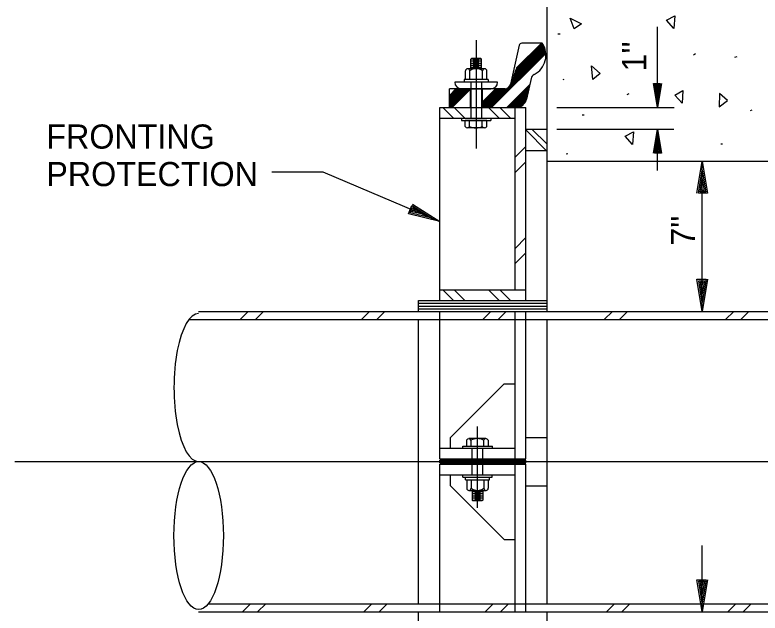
# Model space of a CAD drawing. Extents: x 22388.1 to 22405.7, y 22369.6 to 22390.4.
# Drawn here: x 22393.499 to 22394.947, y 22387.97 to 22389.132 of the extents above; entities that cross this region are included whole.
import ezdxf

# ---------------------------------------------------------------- set-up
doc = ezdxf.new("R2010")
doc.units = 0
for name, color, linetype in [('Level 1', 7, 'Continuous'), ('Level 2', 7, 'Continuous'), ('Level 4', 7, 'Continuous'), ('Level 44', 7, 'Continuous'), ('Level 50', 7, 'Continuous'), ('Level 7', 7, 'Continuous')]:
    doc.layers.add(name, color=color, linetype=linetype)

msp = doc.modelspace()

# ---------------------------------------------------------------- linework, layer by layer
at = {"layer": 'Level 1'}
for p, q in [((22394.7476, 22388.9518), (22394.7476, 22389.1086)), ((22394.3954, 22389.0827), (22394.3954, 22388.872)), ((22394.5267, 22389.0714), (22394.4678, 22389.0125)), ((22394.5264, 22389.072), (22394.4683, 22389.0139)), ((22394.5261, 22389.0726), (22394.4688, 22389.0153)), ((22394.5258, 22389.0732), (22394.4693, 22389.0167)), ((22394.5255, 22389.0738), (22394.4698, 22389.0182)), ((22394.5251, 22389.0744), (22394.4703, 22389.0196)), ((22394.5248, 22389.075), (22394.4708, 22389.021)), ((22394.5244, 22389.0756), (22394.4713, 22389.0224)), ((22394.5241, 22389.0761), (22394.4718, 22389.0239)), ((22394.5237, 22389.0767), (22394.4723, 22389.0253)), ((22394.5229, 22389.0768), (22394.4728, 22389.0267)), ((22394.522, 22389.0768), (22394.4733, 22389.0281)), ((22394.53, 22389.062), (22394.4198, 22388.9518)), ((22394.5301, 22389.0614), (22394.4205, 22388.9518)), ((22394.5302, 22389.0608), (22394.4212, 22388.9518)), ((22394.5303, 22389.0602), (22394.4219, 22388.9518)), ((22394.5304, 22389.0596), (22394.4226, 22388.9518)), ((22394.5305, 22389.0589), (22394.4233, 22388.9518)), ((22394.5306, 22389.0583), (22394.424, 22388.9518)), ((22394.5306, 22389.0577), (22394.4247, 22388.9518)), ((22394.5307, 22389.057), (22394.4254, 22388.9518)), ((22394.5298, 22389.0625), (22394.4606, 22388.9933)), ((22394.5296, 22389.0633), (22394.4618, 22388.9954)), ((22394.5295, 22389.064), (22394.4623, 22388.9968)), ((22394.5293, 22389.0647), (22394.4628, 22388.9982)), ((22394.5291, 22389.0654), (22394.4633, 22388.9997)), ((22394.5288, 22389.0661), (22394.4638, 22389.0011)), ((22394.5286, 22389.0668), (22394.4643, 22389.0025)), ((22394.5284, 22389.0675), (22394.4648, 22389.0039)), ((22394.5281, 22389.0682), (22394.4653, 22389.0054)), ((22394.5279, 22389.0689), (22394.4658, 22389.0068)), ((22394.5276, 22389.0695), (22394.4663, 22389.0082)), ((22394.5273, 22389.0701), (22394.4668, 22389.0096)), ((22394.527, 22389.0708), (22394.4673, 22389.011)), ((22394.385, 22389.0459), (22394.3861, 22389.0471)), ((22394.4058, 22389.0461), (22394.385, 22389.0461)), ((22394.385, 22389.0273), (22394.385, 22389.0459)), ((22394.4047, 22389.0471), (22394.3861, 22389.0471)), ((22394.4006, 22389.044), (22394.3897, 22389.044)), ((22394.4058, 22389.046), (22394.4047, 22389.0471)), ((22394.4058, 22389.0273), (22394.4058, 22389.046)), ((22394.4058, 22389.0419), (22394.385, 22389.0419)), ((22394.4058, 22389.0377), (22394.385, 22389.0377)), ((22394.4058, 22389.0336), (22394.385, 22389.0336)), ((22394.4058, 22389.0294), (22394.385, 22389.0294)), ((22394.4006, 22389.0398), (22394.3897, 22389.0398)), ((22394.4006, 22389.0356), (22394.3897, 22389.0356)), ((22394.4006, 22389.0315), (22394.3897, 22389.0315)), ((22394.3746, 22389.0065), (22394.3746, 22389.0231)), ((22394.3746, 22389.0231), (22394.3746, 22389.0231)), ((22394.412, 22389.0273), (22394.3788, 22389.0273)), ((22394.383, 22389.0065), (22394.383, 22389.0231)), ((22394.4077, 22389.0065), (22394.4077, 22389.0231)), ((22394.4163, 22389.0065), (22394.4163, 22389.0231)), ((22394.4189, 22389.0065), (22394.372, 22389.0065)), ((22394.372, 22389.0065), (22394.372, 22389.0013)), ((22394.385, 22389.0013), (22394.385, 22388.9309)), ((22394.4058, 22389.0013), (22394.4058, 22388.9309)), ((22394.4189, 22389.0065), (22394.4189, 22389.0013)), ((22394.3795, 22388.9882), (22394.3433, 22388.9521)), ((22394.3788, 22388.9882), (22394.3433, 22388.9528)), ((22394.3781, 22388.9882), (22394.3433, 22388.9535)), ((22394.3774, 22388.9882), (22394.3433, 22388.9542)), ((22394.3767, 22388.9882), (22394.3433, 22388.9549)), ((22394.376, 22388.9882), (22394.3433, 22388.9556)), ((22394.3752, 22388.9882), (22394.3433, 22388.9563)), ((22394.3745, 22388.9882), (22394.3433, 22388.957)), ((22394.3738, 22388.9882), (22394.3433, 22388.9578)), ((22394.3731, 22388.9882), (22394.3433, 22388.9585)), ((22394.3724, 22388.9882), (22394.3433, 22388.9592)), ((22394.3717, 22388.9882), (22394.3433, 22388.9599)), ((22394.371, 22388.9882), (22394.3433, 22388.9606)), ((22394.3703, 22388.9882), (22394.3433, 22388.9613)), ((22394.3696, 22388.9882), (22394.3433, 22388.962)), ((22394.3689, 22388.9882), (22394.3433, 22388.9627)), ((22394.3682, 22388.9882), (22394.3433, 22388.9634)), ((22394.3675, 22388.9882), (22394.3433, 22388.9641)), ((22394.3668, 22388.9882), (22394.3433, 22388.9648)), ((22394.3661, 22388.9882), (22394.3433, 22388.9655)), ((22394.3653, 22388.9882), (22394.3433, 22388.9663)), ((22394.3646, 22388.9882), (22394.3433, 22388.9669)), ((22394.3639, 22388.9882), (22394.3433, 22388.9676)), ((22394.3632, 22388.9882), (22394.3433, 22388.9684)), ((22394.3625, 22388.9882), (22394.3433, 22388.9691)), ((22394.3618, 22388.9882), (22394.3433, 22388.9698)), ((22394.3611, 22388.9882), (22394.3433, 22388.9705)), ((22394.3604, 22388.9882), (22394.3433, 22388.9712)), ((22394.3597, 22388.9882), (22394.3433, 22388.9719)), ((22394.359, 22388.9882), (22394.3433, 22388.9726)), ((22394.3583, 22388.9882), (22394.3433, 22388.9733)), ((22394.3576, 22388.9882), (22394.3433, 22388.974)), ((22394.3569, 22388.9882), (22394.3433, 22388.9747)), ((22394.3562, 22388.9882), (22394.3433, 22388.9754)), ((22394.3802, 22388.9882), (22394.3437, 22388.9518)), ((22394.3809, 22388.9882), (22394.3445, 22388.9518)), ((22394.3816, 22388.9882), (22394.3452, 22388.9518)), ((22394.3823, 22388.9882), (22394.3459, 22388.9518)), ((22394.383, 22388.9882), (22394.3466, 22388.9518)), ((22394.3837, 22388.9882), (22394.3473, 22388.9518)), ((22394.3837, 22388.9875), (22394.348, 22388.9518)), ((22394.3837, 22388.9868), (22394.3487, 22388.9518)), ((22394.3837, 22388.9868), (22394.3487, 22388.9518)), ((22394.4435, 22388.9882), (22394.407, 22388.9518)), ((22394.4428, 22388.9882), (22394.4072, 22388.9526)), ((22394.4421, 22388.9882), (22394.4072, 22388.9533)), ((22394.4414, 22388.9882), (22394.4072, 22388.954)), ((22394.4407, 22388.9882), (22394.4072, 22388.9547)), ((22394.44, 22388.9882), (22394.4072, 22388.9554)), ((22394.4393, 22388.9882), (22394.4072, 22388.9561)), ((22394.4386, 22388.9882), (22394.4072, 22388.9568)), ((22394.4378, 22388.9882), (22394.4072, 22388.9575)), ((22394.4371, 22388.9882), (22394.4072, 22388.9583)), ((22394.4364, 22388.9882), (22394.4072, 22388.959)), ((22394.4357, 22388.9882), (22394.4072, 22388.9597)), ((22394.435, 22388.9882), (22394.4072, 22388.9604)), ((22394.4343, 22388.9882), (22394.4072, 22388.9611)), ((22394.4336, 22388.9882), (22394.4072, 22388.9618)), ((22394.4329, 22388.9882), (22394.4072, 22388.9625)), ((22394.4442, 22388.9882), (22394.4078, 22388.9518)), ((22394.4449, 22388.9882), (22394.4085, 22388.9518)), ((22394.4456, 22388.9882), (22394.4092, 22388.9518)), ((22394.4463, 22388.9882), (22394.4099, 22388.9518)), ((22394.447, 22388.9882), (22394.4106, 22388.9518)), ((22394.4478, 22388.9882), (22394.4113, 22388.9518)), ((22394.4485, 22388.9882), (22394.412, 22388.9518)), ((22394.4492, 22388.9882), (22394.4127, 22388.9518)), ((22394.4499, 22388.9882), (22394.4134, 22388.9518)), ((22394.4506, 22388.9882), (22394.4141, 22388.9518)), ((22394.4513, 22388.9882), (22394.4148, 22388.9518)), ((22394.452, 22388.9882), (22394.4155, 22388.9518)), ((22394.4527, 22388.9882), (22394.4162, 22388.9518)), ((22394.4537, 22388.9886), (22394.417, 22388.9518)), ((22394.4548, 22388.9889), (22394.4177, 22388.9518)), ((22394.4559, 22388.9893), (22394.4184, 22388.9518)), ((22394.4576, 22388.9903), (22394.4191, 22388.9518)), ((22394.4553, 22388.9518), (22394.4993, 22388.9957)), ((22394.456, 22388.9518), (22394.4991, 22388.9948)), ((22394.4568, 22388.9518), (22394.4989, 22388.9939)), ((22394.4575, 22388.9518), (22394.4987, 22388.993)), ((22394.4582, 22388.9518), (22394.4985, 22388.9921)), ((22394.4589, 22388.9518), (22394.4983, 22388.9912)), ((22394.4596, 22388.9518), (22394.4981, 22388.9903)), ((22394.4603, 22388.9518), (22394.4979, 22388.9894)), ((22394.461, 22388.9518), (22394.4977, 22388.9884)), ((22394.4617, 22388.9518), (22394.4975, 22388.9875)), ((22394.4624, 22388.9518), (22394.4973, 22388.9866)), ((22394.4631, 22388.9518), (22394.497, 22388.9857)), ((22394.4638, 22388.9518), (22394.4966, 22388.9846)), ((22394.4645, 22388.9518), (22394.4966, 22388.9839)), ((22394.4652, 22388.9518), (22394.4964, 22388.983)), ((22394.4659, 22388.9518), (22394.4962, 22388.9821)), ((22394.4666, 22388.9518), (22394.496, 22388.9812)), ((22394.4674, 22388.9518), (22394.4958, 22388.9803)), ((22394.4681, 22388.9518), (22394.4956, 22388.9793)), ((22394.4954, 22388.9784), (22394.4688, 22388.9518)), ((22394.4952, 22388.9775), (22394.4695, 22388.9518)), ((22394.495, 22388.9766), (22394.4702, 22388.9518)), ((22394.4948, 22388.9757), (22394.4709, 22388.9518)), ((22394.4946, 22388.9748), (22394.4716, 22388.9518)), ((22394.4944, 22388.9739), (22394.4724, 22388.9519)), ((22394.4942, 22388.973), (22394.473, 22388.9518)), ((22394.494, 22388.9721), (22394.4737, 22388.9518)), ((22394.4938, 22388.9711), (22394.4745, 22388.9519)), ((22394.4936, 22388.9702), (22394.4753, 22388.9519)), ((22394.4934, 22388.9693), (22394.4761, 22388.952)), ((22394.4932, 22388.9684), (22394.477, 22388.9522)), ((22394.493, 22388.9675), (22394.4779, 22388.9524)), ((22394.4927, 22388.9665), (22394.4789, 22388.9527)), ((22394.4923, 22388.9654), (22394.4799, 22388.9531)), ((22394.4917, 22388.9639), (22394.4815, 22388.9537)), ((22394.4906, 22388.9619), (22394.4835, 22388.9547)), ((22394.3516, 22388.9309), (22394.3308, 22388.9518)), ((22394.3737, 22388.9309), (22394.3528, 22388.9518)), ((22394.44, 22388.9309), (22394.4191, 22388.9518)), ((22394.462, 22388.9309), (22394.4412, 22388.9518)), ((22394.5523, 22388.9518), (22394.7801, 22388.9518)), ((22394.3668, 22388.9309), (22394.3668, 22388.927)), ((22394.3668, 22388.927), (22394.4241, 22388.927)), ((22394.416, 22388.927), (22394.3743, 22388.927)), ((22394.3743, 22388.9153), (22394.3743, 22388.927)), ((22394.3827, 22388.9152), (22394.3827, 22388.927)), ((22394.4073, 22388.9152), (22394.4073, 22388.927)), ((22394.416, 22388.9153), (22394.416, 22388.927)), ((22394.4241, 22388.9309), (22394.4241, 22388.927)), ((22394.4117, 22388.9125), (22394.3785, 22388.9125)), ((22394.5335, 22388.8667), (22394.4918, 22388.9084)), ((22394.5335, 22388.8804), (22394.5037, 22388.9101)), ((22394.5523, 22388.9101), (22394.7793, 22388.9101)), ((22394.7476, 22388.8298), (22394.7476, 22388.9101)), ((22394.471, 22388.8552), (22394.4918, 22388.8761)), ((22394.471, 22388.8258), (22394.4918, 22388.8466)), ((22394.8346, 22388.5559), (22394.8346, 22388.8476)), ((22394.471, 22388.6784), (22394.4918, 22388.6993)), ((22394.471, 22388.649), (22394.4918, 22388.6698)), ((22394.3516, 22388.5768), (22394.3308, 22388.5976)), ((22394.3736, 22388.5768), (22394.3528, 22388.5976)), ((22394.4399, 22388.5768), (22394.4191, 22388.5976)), ((22394.462, 22388.5768), (22394.4412, 22388.5976)), ((22394.2835, 22388.5716), (22394.5335, 22388.5716)), ((22394.2835, 22388.5664), (22394.5335, 22388.5664)), ((22393.9371, 22388.5403), (22393.9528, 22388.5559)), ((22393.9666, 22388.5403), (22393.9822, 22388.5559)), ((22394.1728, 22388.5403), (22394.1885, 22388.5559)), ((22394.2023, 22388.5403), (22394.2179, 22388.5559)), ((22394.2835, 22388.5611), (22394.5335, 22388.5611)), ((22394.4085, 22388.5403), (22394.4242, 22388.5559)), ((22394.438, 22388.5403), (22394.4536, 22388.5559)), ((22394.6442, 22388.5403), (22394.6599, 22388.5559)), ((22394.6737, 22388.5403), (22394.6893, 22388.5559)), ((22394.8799, 22388.5403), (22394.8956, 22388.5559)), ((22394.9094, 22388.5403), (22394.925, 22388.5559)), ((22394.3979, 22388.1746), (22394.3979, 22388.3321)), ((22394.3768, 22388.306), (22394.3768, 22388.2942)), ((22394.4142, 22388.3088), (22394.381, 22388.3088)), ((22394.3852, 22388.306), (22394.3852, 22388.2942)), ((22394.4098, 22388.3061), (22394.4098, 22388.2942)), ((22394.4185, 22388.306), (22394.4185, 22388.2942)), ((22394.3696, 22388.2942), (22394.4269, 22388.2942)), ((22394.3696, 22388.2903), (22394.3696, 22388.2942)), ((22394.3875, 22388.2382), (22394.3875, 22388.2903)), ((22394.4083, 22388.2382), (22394.4083, 22388.2903)), ((22394.4269, 22388.2903), (22394.4269, 22388.2942)), ((22393.4995, 22388.2643), (22396.3902, 22388.2643)), ((22394.3251, 22388.2669), (22394.4918, 22388.2669)), ((22394.3251, 22388.2617), (22394.3251, 22388.2669)), ((22394.3251, 22388.2617), (22394.4918, 22388.2617)), ((22394.4918, 22388.2617), (22394.4918, 22388.2669)), ((22394.3693, 22388.2343), (22394.3693, 22388.2382)), ((22394.3693, 22388.2343), (22394.4266, 22388.2343)), ((22394.3745, 22388.2291), (22394.3745, 22388.2343)), ((22394.4214, 22388.2291), (22394.4214, 22388.2343)), ((22394.4266, 22388.2343), (22394.4266, 22388.2382)), ((22394.3745, 22388.2291), (22394.4214, 22388.2291)), ((22394.3771, 22388.2291), (22394.3771, 22388.2125)), ((22394.3857, 22388.2291), (22394.3857, 22388.2125)), ((22394.4103, 22388.2291), (22394.4103, 22388.2125)), ((22394.4188, 22388.2291), (22394.4188, 22388.2125)), ((22394.3813, 22388.2083), (22394.4146, 22388.2083)), ((22394.3875, 22388.2083), (22394.3875, 22388.1895)), ((22394.3875, 22388.2062), (22394.4083, 22388.2062)), ((22394.3927, 22388.2041), (22394.4037, 22388.2041)), ((22394.4083, 22388.2083), (22394.4083, 22388.1896)), ((22394.3875, 22388.202), (22394.4083, 22388.202)), ((22394.3875, 22388.1978), (22394.4083, 22388.1978)), ((22394.3875, 22388.1937), (22394.4083, 22388.1937)), ((22394.3875, 22388.1895), (22394.3886, 22388.1885)), ((22394.3875, 22388.1895), (22394.4083, 22388.1895)), ((22394.3886, 22388.1885), (22394.4073, 22388.1885)), ((22394.3927, 22388.1999), (22394.4037, 22388.1999)), ((22394.3927, 22388.1958), (22394.4037, 22388.1958)), ((22394.3927, 22388.1916), (22394.4037, 22388.1916)), ((22394.4083, 22388.1896), (22394.4073, 22388.1885)), ((22394.8346, 22387.9726), (22394.8346, 22388.101)), ((22393.9416, 22387.9726), (22393.9572, 22387.9882)), ((22393.971, 22387.9726), (22393.9867, 22387.9882)), ((22394.1773, 22387.9726), (22394.1929, 22387.9882)), ((22394.2067, 22387.9726), (22394.2224, 22387.9882)), ((22394.413, 22387.9726), (22394.4286, 22387.9882)), ((22394.4424, 22387.9726), (22394.4581, 22387.9882)), ((22394.6487, 22387.9726), (22394.6643, 22387.9882)), ((22394.6781, 22387.9726), (22394.6938, 22387.9882)), ((22394.8844, 22387.9726), (22394.9, 22387.9882)), ((22394.9138, 22387.9726), (22394.9295, 22387.9882))]:
    msp.add_line(p, q, dxfattribs=at)
for centre, radius, start, end in [((22394.3788, 22389.023), 0.00421, 0.4975, 179.5025), ((22394.3953, 22389.007), 0.0203, 52.4343, 127.5657), ((22394.412, 22389.023), 0.00422, 0.5659, 179.4342), ((22394.3785, 22388.9171), 0.00456, 202.8005, 337.625), ((22394.3951, 22388.9409), 0.0285, 244.116, 295.4481), ((22394.4116, 22388.9171), 0.00469, 204.0009, 336.8325), ((22394.381, 22388.3042), 0.00456, 22.375, 157.1995), ((22394.3976, 22388.2803), 0.0285, 64.5519, 115.884), ((22394.4141, 22388.3041), 0.00469, 23.1675, 155.9991), ((22394.3813, 22388.2125), 0.00422, 180.5659, 359.4341), ((22394.398, 22388.2286), 0.0203, 232.4343, 307.5657), ((22394.4146, 22388.2125), 0.00421, 180.4975, 359.5025)]:
    msp.add_arc(centre, radius, start, end, dxfattribs=at)
msp.add_ellipse((22393.8564, 22388.408), major_axis=(0, 0.1438), ratio=0.333333, start_param=0, end_param=3.141593, dxfattribs=at)
msp.add_ellipse((22393.8564, 22388.1205), major_axis=(0, -0.1438), ratio=0.333333, dxfattribs=at)
at = {"layer": 'Level 2'}
for p, q in [((22394.4792, 22389.0727), (22394.4623, 22388.9974)), ((22394.5236, 22389.0768), (22394.4842, 22389.0768)), ((22394.4371, 22389.0013), (22394.3538, 22389.0013)), ((22394.5021, 22389.0084), (22394.4931, 22388.9681)), ((22394.4509, 22388.9882), (22394.3433, 22388.9882)), ((22394.3433, 22388.9518), (22394.3433, 22388.9882)), ((22394.3668, 22388.9882), (22394.4241, 22388.9882)), ((22394.3837, 22388.9882), (22394.3837, 22388.9518)), ((22394.4072, 22388.9882), (22394.4072, 22388.9518)), ((22394.7476, 22388.9648), (22394.7476, 22388.9648)), ((22394.3251, 22388.9518), (22394.4918, 22388.9518)), ((22394.3251, 22388.5768), (22394.3251, 22388.9518)), ((22394.3433, 22388.9518), (22394.4728, 22388.9518)), ((22394.471, 22388.5976), (22394.471, 22388.9518)), ((22394.4918, 22388.5768), (22394.4918, 22388.9518)), ((22394.7476, 22388.9518), (22394.7476, 22388.9518)), ((22394.3251, 22388.9309), (22394.471, 22388.9309)), ((22394.4918, 22388.9101), (22394.5335, 22388.9101)), ((22394.5335, 22388.5559), (22394.5335, 22388.9101)), ((22394.7476, 22388.9101), (22394.7476, 22388.9101)), ((22394.7476, 22388.8971), (22394.7476, 22388.8971)), ((22394.4918, 22388.8684), (22394.5335, 22388.8684)), ((22394.8346, 22388.8476), (22394.8346, 22388.8476)), ((22394.8346, 22388.8303), (22394.8346, 22388.8303)), ((22394.3092, 22388.7373), (22394.3092, 22388.7373)), ((22394.3251, 22388.7306), (22394.3251, 22388.7306)), ((22394.3251, 22388.5976), (22394.4918, 22388.5976)), ((22394.2835, 22388.5768), (22394.5335, 22388.5768)), ((22394.2835, 22388.5559), (22394.2835, 22388.5768)), ((22394.8346, 22388.5733), (22394.8346, 22388.5733)), ((22393.8564, 22388.5559), (22395.5855, 22388.5559)), ((22394.3251, 22388.2695), (22394.3251, 22388.5559)), ((22394.471, 22388.2695), (22394.471, 22388.5559)), ((22394.4918, 22388.2695), (22394.4918, 22388.5559)), ((22394.8346, 22388.5559), (22394.8346, 22388.5559)), ((22393.8376, 22388.5403), (22395.5668, 22388.5403)), ((22394.2835, 22387.9882), (22394.2835, 22388.5403)), ((22394.5335, 22387.9882), (22394.5335, 22388.5403)), ((22394.3458, 22388.3111), (22394.45, 22388.4153)), ((22394.45, 22388.4153), (22394.4708, 22388.4153)), ((22394.3458, 22388.2903), (22394.3458, 22388.3111)), ((22394.4918, 22388.3111), (22394.5335, 22388.3111)), ((22394.3251, 22388.2903), (22394.471, 22388.2903)), ((22394.3251, 22388.2695), (22394.4918, 22388.2695)), ((22394.3251, 22388.2591), (22394.4918, 22388.2591)), ((22394.3251, 22387.9726), (22394.3251, 22388.2591)), ((22394.471, 22387.9726), (22394.471, 22388.2591)), ((22394.4918, 22387.9726), (22394.4918, 22388.2591)), ((22394.3251, 22388.2382), (22394.471, 22388.2382)), ((22394.3458, 22388.2174), (22394.3458, 22388.2382)), ((22394.3458, 22388.2174), (22394.45, 22388.1132)), ((22394.4918, 22388.2174), (22394.5335, 22388.2174)), ((22394.45, 22388.1132), (22394.4708, 22388.1132)), ((22393.8751, 22387.9882), (22395.6043, 22387.9882)), ((22394.8346, 22387.9899), (22394.8346, 22387.9899)), ((22393.8564, 22387.9726), (22395.5855, 22387.9726)), ((22394.2835, 22387.9518), (22394.2835, 22387.9726)), ((22394.5335, 22387.6184), (22394.5335, 22387.9726)), ((22394.8346, 22387.9726), (22394.8346, 22387.9726))]:
    msp.add_line(p, q, dxfattribs=at)
for points in [[(22394.7554, 22388.9985), (22394.7476, 22388.9518), (22394.7399, 22388.9985), (22394.7531, 22388.9985), (22394.7476, 22388.9648), (22394.7424, 22388.9965), (22394.7509, 22388.9965), (22394.7476, 22388.9773), (22394.7449, 22388.9945), (22394.7484, 22388.9945), (22394.7476, 22388.9903)], [(22394.7399, 22388.8634), (22394.7476, 22388.9101), (22394.7554, 22388.8634), (22394.7421, 22388.8634), (22394.7476, 22388.8971), (22394.7529, 22388.8654), (22394.7444, 22388.8654), (22394.7476, 22388.8846), (22394.7504, 22388.8674), (22394.7469, 22388.8674), (22394.7476, 22388.8716)], [(22394.8242, 22388.7853), (22394.8346, 22388.8476), (22394.8449, 22388.7853), (22394.8272, 22388.7853), (22394.8346, 22388.8303), (22394.8416, 22388.7879), (22394.8302, 22388.7879), (22394.8346, 22388.8136), (22394.8382, 22388.7906), (22394.8336, 22388.7906), (22394.8346, 22388.7963)], [(22393.9983, 22388.8271), (22394.0973, 22388.8271), (22394.3251, 22388.7306)], [(22394.2718, 22388.7644), (22394.3251, 22388.7306), (22394.2637, 22388.7454), (22394.2706, 22388.7616), (22394.3092, 22388.7373), (22394.2675, 22388.7474), (22394.2719, 22388.7578), (22394.2938, 22388.7438), (22394.2712, 22388.7494), (22394.273, 22388.7537), (22394.2778, 22388.7506)], [(22394.8449, 22388.6183), (22394.8346, 22388.5559), (22394.8242, 22388.6183), (22394.8419, 22388.6183), (22394.8346, 22388.5733), (22394.8276, 22388.6156), (22394.8389, 22388.6156), (22394.8346, 22388.5899), (22394.8309, 22388.6129), (22394.8356, 22388.6129), (22394.8346, 22388.6073)], [(22394.8449, 22388.0349), (22394.8346, 22387.9726), (22394.8242, 22388.0349), (22394.8419, 22388.0349), (22394.8346, 22387.9899), (22394.8276, 22388.0323), (22394.8389, 22388.0323), (22394.8346, 22388.0066), (22394.8309, 22388.0296), (22394.8356, 22388.0296), (22394.8346, 22388.0239)]]:
    msp.add_lwpolyline(points, dxfattribs=at)
for centre, radius, start, end in [((22394.4842, 22389.0716), 0.00521, 90, 167.3821), ((22394.4892, 22389.0533), 0.0417, 297.1705, 34.2289), ((22394.5136, 22389.0058), 0.0117, 117.1705, 167.3835), ((22394.3668, 22389.0012), 0.013, 180, 270), ((22394.4241, 22389.0012), 0.013, 270, 0), ((22394.4509, 22389), 0.0117, 270, 347.3806), ((22394.4728, 22388.9726), 0.0208, 270, 347.3827)]:
    msp.add_arc(centre, radius, start, end, dxfattribs=at)
at = {"layer": 'Level 44'}
for p, q in [((22394.5541, 22389.095), (22394.5586, 22389.095)), ((22394.8175, 22389.0543), (22394.8212, 22389.0565)), ((22394.898, 22389.05), (22394.9023, 22389.0508)), ((22394.564, 22389.0069), (22394.5655, 22389.0065)), ((22394.6889, 22388.9769), (22394.6926, 22388.9792)), ((22394.9281, 22388.9459), (22394.9317, 22388.9476)), ((22394.6015, 22388.9379), (22394.6052, 22388.9376)), ((22394.7478, 22388.8888), (22394.7515, 22388.8911)), ((22394.8705, 22388.8812), (22394.8739, 22388.8814)), ((22394.5699, 22388.8617), (22394.5732, 22388.8623))]:
    msp.add_line(p, q, dxfattribs=at)
for points in [[(22394.7794, 22389.1056), (22394.7651, 22389.1216), (22394.781, 22389.1301)], [(22394.5856, 22389.1048), (22394.5777, 22389.1252), (22394.5998, 22389.1144)], [(22394.6194, 22389.033), (22394.6364, 22389.0181), (22394.6223, 22389.0062)], [(22394.7955, 22388.9602), (22394.7812, 22388.9762), (22394.7971, 22388.9847)], [(22394.8674, 22388.9533), (22394.8834, 22388.9654), (22394.868, 22388.979)], [(22394.699, 22388.88), (22394.6848, 22388.896), (22394.7007, 22388.9045)]]:
    msp.add_lwpolyline(points, close=True, dxfattribs=at)
at = {"layer": 'Level 50'}
msp.add_line((22394.4188, 22388.2125), (22394.4188, 22388.2125), dxfattribs=at)
at = {"layer": 'Level 7'}
for p, q in [((22394.5335, 22388.5559), (22394.5335, 22389.9643)), ((22394.5335, 22388.8476), (22395.0335, 22388.8476)), ((22394.5335, 22387.9882), (22394.5335, 22388.5403)), ((22394.5335, 22386.2627), (22394.5335, 22387.9726))]:
    msp.add_line(p, q, dxfattribs=at)

# ---------------------------------------------------------------- texts
at = {"layer": 'Level 4'}
for s, p in [("1''", (22394.7257, 22389.0217)), ("7''", (22394.8207, 22388.6833))]:
    msp.add_text(s, height=0.04688, rotation=90, dxfattribs=at).set_placement(p)
for s, p in [('FRONTING', (22393.5605, 22388.8721)), ('PROTECTION', (22393.5605, 22388.7992))]:
    msp.add_text(s, height=0.04688, dxfattribs=at).set_placement(p)

doc.saveas('drawing.dxf')
